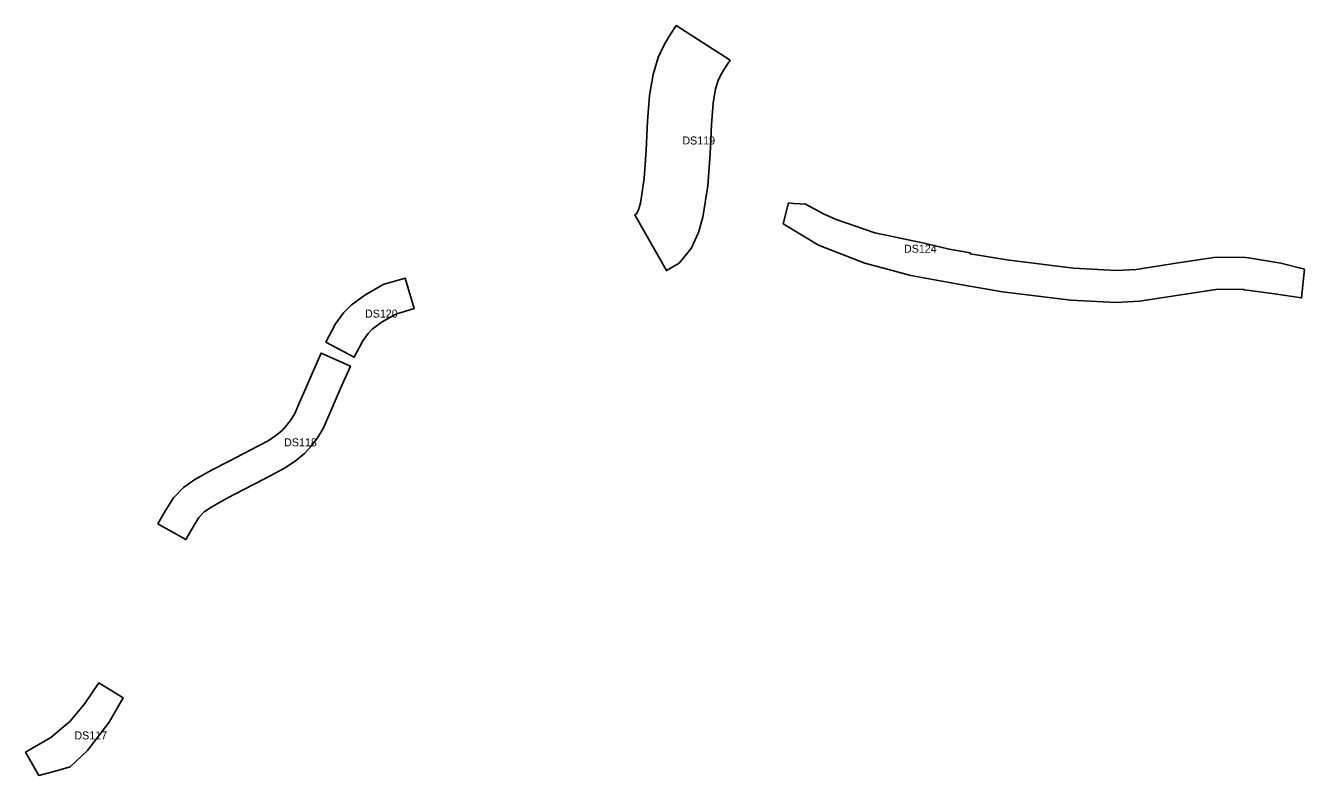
# Model space of a CAD drawing. Extents: x -546777 to -486947, y -1193757 to -1133234.
# Drawn here: x -525551 to -517564, y -1190733 to -1186049 of the extents above; entities that cross this region are included whole.
import ezdxf

# ---------------------------------------------------------------- set-up
doc = ezdxf.new("R2010")
doc.units = 0
doc.layers.add('01 - silnice', color=7, linetype='Continuous')

msp = doc.modelspace()

# ---------------------------------------------------------------- linework, layer by layer
at = {"layer": '01 - silnice'}
for points in [[(-521468.17, -1187533.53), (-521548.17, -1187579.24), (-521746.59, -1187231.92), (-521734.96, -1187225.27), (-521723.69, -1187201.01), (-521711.23, -1187158.29), (-521687, -1187005.33), (-521674.22, -1186826.85), (-521665.97, -1186645.45), (-521653.73, -1186484.96), (-521632.07, -1186354.41), (-521600.24, -1186248.39), (-521560.68, -1186164.53), (-521522.29, -1186102.53), (-521487.93, -1186049.06), (-521151.4, -1186265.27), (-521183.96, -1186315.95), (-521208.63, -1186355.77), (-521225.72, -1186392.02), (-521241.63, -1186445.01), (-521256.23, -1186533), (-521266.66, -1186669.75), (-521274.87, -1186850.22), (-521289.24, -1187050.99), (-521320.13, -1187245.94), (-521348.16, -1187342.05), (-521394.8, -1187442.47)], [(-519006.29, -1187564.97), (-518739.02, -1187578.66), (-518614.79, -1187571.85), (-518352.34, -1187531.86), (-518115.55, -1187495.77), (-517932.84, -1187498.68), (-517912.28, -1187500.58), (-517711.98, -1187532.83), (-517563.9, -1187570.88), (-517582.05, -1187750.8), (-517751.09, -1187724.88), (-517937.42, -1187699.11), (-517943.66, -1187698.53), (-518101.98, -1187696.01), (-518322.21, -1187729.57), (-518594.21, -1187771.02), (-518738.66, -1187778.94), (-519023.75, -1187764.34), (-519450.5, -1187711.32), (-519701.61, -1187668.83), (-519769.97, -1187655.98), (-520021.69, -1187610.43), (-520309.36, -1187533.72), (-520599.44, -1187421.04), (-520819.99, -1187286.79), (-520786.18, -1187156.93), (-520755.24, -1187161.21), (-520712.78, -1187161.63), (-520680.95, -1187164.53), (-520568.27, -1187224.46), (-520489.16, -1187260.42), (-520247.03, -1187344.33), (-519937.78, -1187409.06), (-519781.96, -1187445.02), (-519650.45, -1187468.07), (-519651.72, -1187474.43), (-519421.47, -1187513.39)], [(-523444.48, -1188018.82), (-523498.38, -1188120.72), (-523675.17, -1188027.2), (-523614.92, -1187913.29), (-523564.73, -1187843.32), (-523517.71, -1187794.75), (-523432.96, -1187732.56), (-523318.33, -1187667.44), (-523181.21, -1187626.03), (-523123.39, -1187817.49), (-523239.04, -1187852.42), (-523324.04, -1187900.7), (-523385.77, -1187946), (-523410.8, -1187971.85)], [(-524504.86, -1189179.76), (-524549.62, -1189259.89), (-524724.22, -1189162.35), (-524677.21, -1189078.2), (-524627.7, -1188998.43), (-524564.43, -1188933.63), (-524493.83, -1188884.42), (-524385.69, -1188825.05), (-524283.31, -1188772.66), (-524148.12, -1188701.54), (-524036.08, -1188642.13), (-523987.32, -1188609.11), (-523948.26, -1188577.58), (-523921.98, -1188547.61), (-523892.11, -1188509.77), (-523870.27, -1188473.38), (-523846.36, -1188419.19), (-523801.08, -1188314.51), (-523761.39, -1188222.1), (-523705.71, -1188095.44), (-523522.62, -1188175.94), (-523577.96, -1188301.81), (-523617.41, -1188393.67), (-523663.09, -1188499.25), (-523692.33, -1188565.55), (-523727.19, -1188623.65), (-523768.2, -1188675.59), (-523809.24, -1188722.39), (-523868.23, -1188770.01), (-523932.87, -1188813.77), (-524054.71, -1188878.39), (-524191.2, -1188950.19), (-524291.99, -1189001.76), (-524388.21, -1189054.6), (-524434.55, -1189086.9), (-524469.32, -1189122.5)], [(-525381.74, -1190710.72), (-525467.74, -1190733.29), (-525550.94, -1190587.22), (-525393.32, -1190496.89), (-525271.91, -1190394.95), (-525181.4, -1190283.47), (-525092.41, -1190153.84), (-524941.5, -1190247.68), (-525028.56, -1190401.49), (-525164.96, -1190576.58), (-525273.3, -1190679.12)]]:
    msp.add_lwpolyline(points, close=True, dxfattribs=at)

# ---------------------------------------------------------------- texts
for s, rotation, p in [('DS119', 0, (-521449, -1186791.9)), ('DS120', 360, (-523431.11, -1187873.38)), ('DS118', 360, (-523936.56, -1188677.66)), ('DS117', 0, (-525246.22, -1190508.4))]:
    msp.add_text(s, height=50, rotation=rotation, dxfattribs=at).set_placement(p)
msp.add_text('DS124', height=50, dxfattribs=at).set_placement((-520064.97, -1187467.94))

doc.saveas('drawing.dxf')
